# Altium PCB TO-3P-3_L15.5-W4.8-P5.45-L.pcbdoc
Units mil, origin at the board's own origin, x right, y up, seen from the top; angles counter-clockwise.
Board outline 1120 x 691.34 mil, 2 copper layers (Top Layer, Bottom Layer), stack 0 mil thick; 1 components, 0 nets, 3 pads, 0 vias.
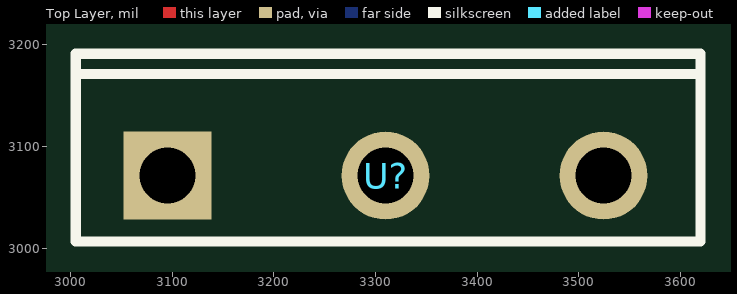
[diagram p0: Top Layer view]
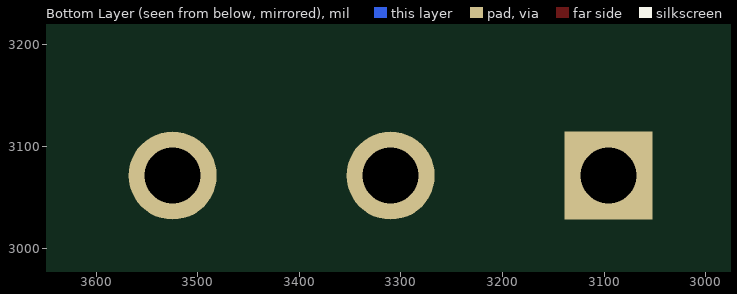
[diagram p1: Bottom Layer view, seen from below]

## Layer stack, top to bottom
Top Layer: signal copper (thickness not stored)
Bottom Layer: signal copper (thickness not stored)

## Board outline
3870,2750 2750,2750 2750,3441.34 3870,3441.34

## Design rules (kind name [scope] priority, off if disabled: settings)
PasteMaskExpansion "Paste Mask Expansion" [All] p1: expansion=0
SolderMaskExpansion "Solder Mask Expansion" [IsVia] p1: expansion=-1000 istentingtop=TRUE
SolderMaskExpansion "Solder Mask Expansion" [All] p2: expansion=2 istentingtop=FALSE

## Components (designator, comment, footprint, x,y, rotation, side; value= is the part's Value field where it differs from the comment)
U? "" TO-3P-3_L15.5-W4.8-P5.45-L 3310,3071.26 r0 top

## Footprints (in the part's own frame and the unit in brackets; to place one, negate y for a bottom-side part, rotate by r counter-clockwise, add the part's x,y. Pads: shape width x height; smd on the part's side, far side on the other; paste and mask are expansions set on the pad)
TO-3P-3_L15.5-W4.8-P5.45-L [mm]
  rect 2.2x2.2 hole 1.4: 1(-5.45,0)
  round 2.2 hole 1.4: 2(0,0) 3(5.45,0)
  silkscreen extent -7.75,-1.65 7.87,3.05

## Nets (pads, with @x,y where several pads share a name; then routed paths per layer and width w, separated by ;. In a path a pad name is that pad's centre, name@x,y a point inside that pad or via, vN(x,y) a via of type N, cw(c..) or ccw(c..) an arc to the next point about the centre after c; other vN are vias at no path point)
pads on no net: U?.1 U?.2 U?.3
